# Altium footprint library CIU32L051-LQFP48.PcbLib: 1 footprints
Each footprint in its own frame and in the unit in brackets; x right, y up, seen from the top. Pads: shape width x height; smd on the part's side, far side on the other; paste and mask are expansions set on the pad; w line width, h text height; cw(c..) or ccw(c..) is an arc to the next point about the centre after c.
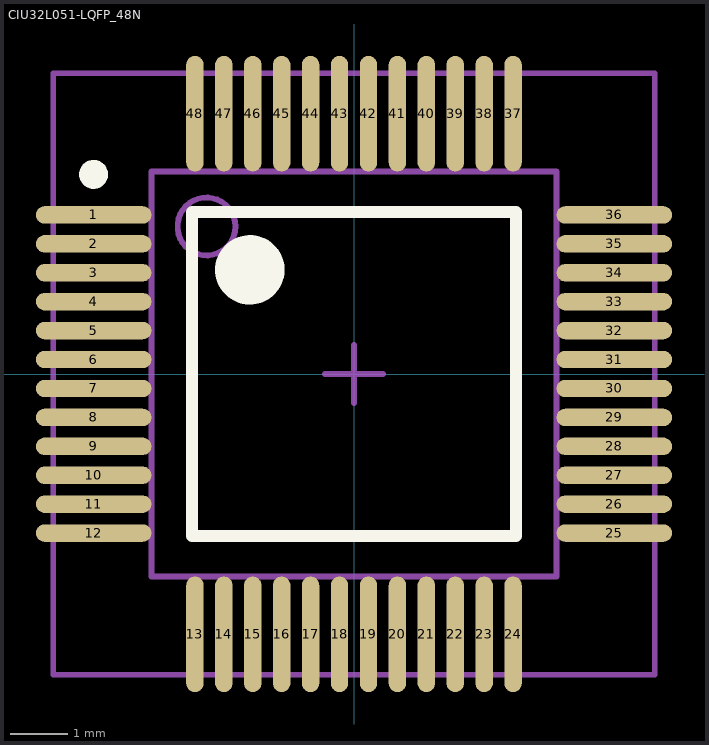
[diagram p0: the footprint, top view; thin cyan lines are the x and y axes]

## CIU32L051-LQFP_48N [mm]
height 1.6
pads (48):
  oval 2x0.3 smd: 1(-4.5,2.75) 2(-4.5,2.25) 3(-4.5,1.75) 4(-4.5,1.25) 5(-4.5,0.75) 6(-4.5,0.25) 7(-4.5,-0.25) 8(-4.5,-0.75) 9(-4.5,-1.25) 10(-4.5,-1.75) 11(-4.5,-2.25) 12(-4.5,-2.75) 25(4.5,-2.75) 26(4.5,-2.25) 27(4.5,-1.75) 28(4.5,-1.25) 29(4.5,-0.75) 30(4.5,-0.25) 31(4.5,0.25) 32(4.5,0.75) 33(4.5,1.25) 34(4.5,1.75) 35(4.5,2.25) 36(4.5,2.75)
  oval 0.3x2 smd: 13(-2.75,-4.5) 14(-2.25,-4.5) 15(-1.75,-4.5) 16(-1.25,-4.5) 17(-0.75,-4.5) 18(-0.25,-4.5) 19(0.25,-4.5) 20(0.75,-4.5) 21(1.25,-4.5) 22(1.75,-4.5) 23(2.25,-4.5) 24(2.75,-4.5) 37(2.75,4.5) 38(2.25,4.5) 39(1.75,4.5) 40(1.25,4.5) 41(0.75,4.5) 42(0.25,4.5) 43(-0.25,4.5) 44(-0.75,4.5) 45(-1.25,4.5) 46(-1.75,4.5) 47(-2.25,4.5) 48(-2.75,4.5)
Top Overlay:
  circle w0.6: c-1.8,1.8 r0.3
  circle w0.25: c-4.5,3.45 r0.125
  lines w0.2: -2.8,-2.8 2.8,-2.8 2.8,2.8 -2.8,2.8 -2.8,-2.8
Mechanical 13:
  circle w0.1: c-2.55,2.55 r0.5
  lines w0.1: -3.5,-3.5 3.5,-3.5 3.5,3.5 -3.5,3.5 -3.5,-3.5
Mechanical 15:
  lines w0.1: -0.5,0 0.5,0 ; 0,-0.5 0,0.5 ; -5.2,-5.2 5.2,-5.2 5.2,5.2 -5.2,5.2 -5.2,-5.2
3D body: height 1.6, standoff 0.15, extent -3.5,-3.5 3.5,3.5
